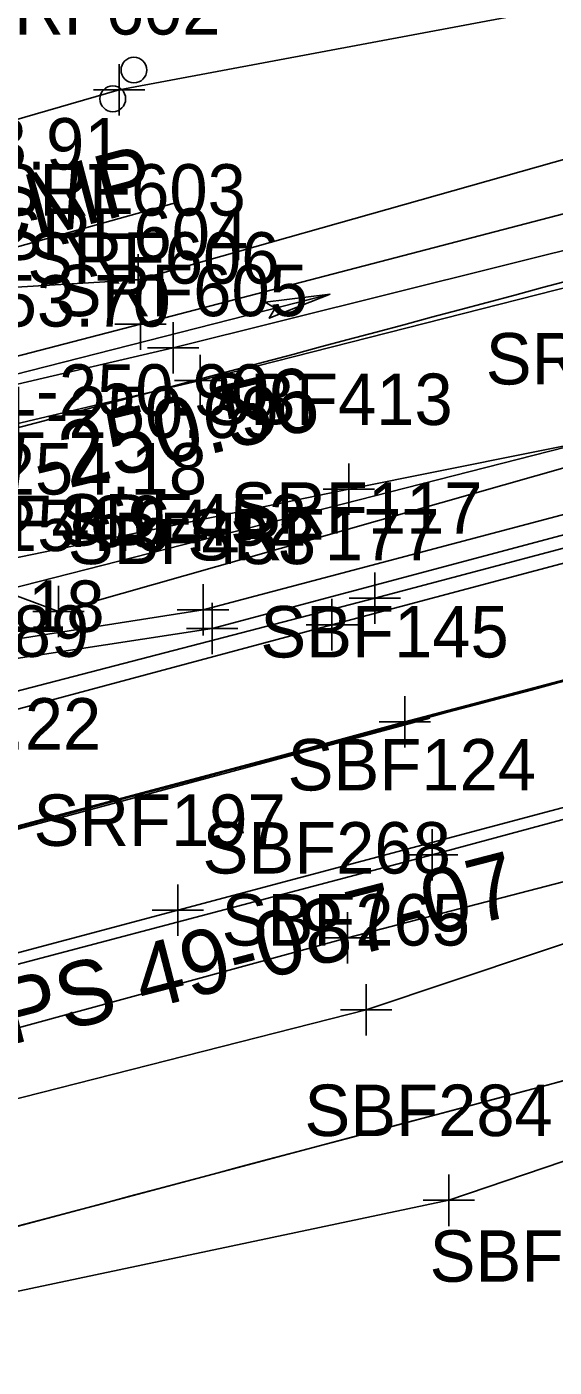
# Model space of a CAD drawing. Extents: x 818717 to 846077, y 440014 to 541392.
# Drawn here: x 831575.4 to 831616.5, y 493028.8 to 493133.1 of the extents above; entities that cross this region are included whole.
import ezdxf

# ---------------------------------------------------------------- set-up
doc = ezdxf.new("R2010")
doc.units = 0
for name, color, linetype in [('SURVEY - CENTERLINE - Preliminary', 7, 'Continuous'), ('SURVEY - CENTERLINE - Preliminary Text', 7, 'Continuous'), ('SURVEY - CONTROL with Text', 7, 'Continuous'), ('SURVEY - DRAINAGE - Area Shapes', 7, 'Continuous'), ('SURVEY - DRAINAGE - Natural Features Text', 7, 'Continuous'), ('SURVEY - DRAINAGE - Pipes and Culverts', 7, 'Continuous'), ('SURVEY - DTM - Breaklines', 7, 'Continuous'), ('SURVEY - DTM - Breaklines - Points - Elevations', 7, 'Continuous'), ('SURVEY - DTM - Breaklines - Points - Locators', 7, 'Continuous'), ('SURVEY - DTM - Breaklines - Points - Numbers', 7, 'Continuous'), ('SURVEY - DTM - Spot Points - Locators', 7, 'Continuous'), ('SURVEY - DTM - Spot Points - Point Numbers', 7, 'Continuous'), ('SURVEY - PROPERTY - ROW Lines', 7, 'Continuous'), ('SURVEY - TRAFFIC CONTROL - Pavement Marking - Points - Locators', 7, 'Continuous'), ('SURVEY - TRAFFIC CONTROL - Pavement Marking - Points - Numbers', 7, 'Continuous'), ('SURVEY - TRAFFIC CONTROL - Pavement Marking with Text', 7, 'Continuous'), ('SURVEY - TRANSPORTATION - Features - Points - Elevations', 7, 'Continuous'), ('SURVEY - TRANSPORTATION - Roads', 7, 'Continuous'), ('SURVEY - TRANSPORTATION - Roads - Points - Locators', 7, 'Continuous'), ('SURVEY - TRANSPORTATION - Roads - Points - Numbers', 7, 'Continuous'), ('SURVEY - UTILITIES - Electric (Overhead) with Text', 7, 'Continuous'), ('SURVEY - UTILITIES - Telephone (Underground) - Points - Locators', 7, 'Continuous'), ('SURVEY - UTILITIES - Telephone (Underground) - Points - Numbers', 7, 'Continuous'), ('SURVEY - UTILITIES - Telephone (Underground) with Text', 7, 'Continuous'), ('SURVEY - UTILITIES - Water with Text', 7, 'Continuous'), ('SURVEY - VEGETATION - Features - Points - Locators', 7, 'Continuous'), ('SURVEY - VEGETATION - Features - Points - Numbers', 7, 'Continuous'), ('SURVEY - VEGETATION - Features with Text', 7, 'Continuous')]:
    doc.layers.add(name, color=color, linetype=linetype)

msp = doc.modelspace()

# ---------------------------------------------------------------- linework, layer by layer
at = {"layer": 'SURVEY - CENTERLINE - Preliminary'}
msp.add_arc((818719.06, 541389.92), 50000, 284.715407, 285.043654, dxfattribs=at)
msp.add_arc((818719.06, 541389.92), 50000, 284.715407, 285.043654, dxfattribs=at)
msp.add_arc((818719.06, 541389.92), 50000, 284.715407, 285.043654, dxfattribs=at)
msp.add_arc((818719.06, 541389.92), 50000, 284.715407, 285.043654, dxfattribs=at)
at = {"layer": 'SURVEY - CENTERLINE - Preliminary Text'}
msp.add_line((831558.49, 493066.32), (831606.78, 493079.3), dxfattribs=at)
at = {"layer": 'SURVEY - DRAINAGE - Area Shapes'}
msp.add_lwpolyline([(833331.86, 493535.43), (832825.85, 493400.54), (832121.68, 493216.64), (831495.16, 493049.75), (830960.37, 492909.24), (830124.73, 492686.08), (830069.9, 493396.23), (830870.86, 494031.84), (831248.11, 494413.67), (831536.95, 494545.33), (832050.07, 494534.01), (832097.96, 494614.84), (832139.36, 494784.62), (832167.46, 494840.58), (832274.31, 494844.36), (832647.22, 494804.13), (832934.24, 494910.41), (833081.03, 494456.05), (833331.86, 493535.43)], dxfattribs=at)
at = {"layer": 'SURVEY - DRAINAGE - Natural Features Text'}
for p, q in [((831599.03, 493112.28), (831572.31, 493105.48)), ((831596.41, 493111.62), (831599.03, 493112.28))]:
    msp.add_line(p, q, dxfattribs=at)
msp.add_lwpolyline([(831599.03, 493112.28), (831594.29, 493110.41), (831594.76, 493111.2), (831593.97, 493111.67)], close=True, dxfattribs=at)
msp.add_lwpolyline([(831599.03, 493112.28), (831594.29, 493110.41), (831594.76, 493111.2), (831593.97, 493111.67), (831599.03, 493112.28)], dxfattribs=at)
at = {"layer": 'SURVEY - DRAINAGE - Pipes and Culverts'}
msp.add_lwpolyline([(831587.19, 493119.44), (831562.39, 493112.53), (831553.15, 493099.33)], dxfattribs=at)
at = {"layer": 'SURVEY - DTM - Breaklines'}
for points in [[(831744.45, 493161.42), (831733.6, 493161.48), (831718.89, 493162.93), (831693.15, 493143.85), (831664.48, 493135.93), (831635.81, 493128.01), (831584.09, 493113.39), (831556.94, 493111.76)], [(831746.03, 493150.49), (831721.99, 493159.6), (831701.71, 493140.66), (831669.96, 493132.34), (831637.08, 493123.71), (831584.27, 493109.95), (831564.6, 493104.83)], [(831745, 493144.97), (831720.93, 493155.22), (831703.76, 493138.42), (831670.77, 493129.62), (831637.8, 493120.82), (831586.82, 493108.1), (831565.35, 493103.1)], [(831741.37, 493141.89), (831719.21, 493148.15), (831699.03, 493131.87), (831668.03, 493124.84), (831637.03, 493117.81), (831588.92, 493105.57), (831559.77, 493098.7)], [(831739.77, 493125.73), (831736.96, 493133.25), (831706.03, 493122.21), (831667.13, 493111.4), (831622.43, 493100.26), (831577.9, 493087.61), (831559.93, 493094.31)], [(831172.33, 492965.05), (831181.59, 492967.43), (831227.67, 492979.44), (831274.72, 492991.66), (831322.92, 493004.21), (831368.33, 493016.26), (831413.81, 493028.29), (831465.87, 493041.9), (831511.63, 493053.91), (831556.79, 493065.9), (831604.84, 493079.03), (831650.91, 493091.16), (831699.1, 493103.99), (831742.48, 493115.71)], [(831735.74, 492991.87), (831733.95, 493031.6), (831721.42, 493066.61), (831712.04, 493082.17), (831703.34, 493084.91), (831695.58, 493084.59), (831648.81, 493072.35), (831601.83, 493056.63), (831555.35, 493044.81), (831504.59, 493031.55), (831455.34, 493020.07), (831405.51, 493005.85), (831372.59, 492995.58), (831358.62, 492993.34)], [(831661.1, 493078), (831648.02, 493074.6), (831600.39, 493062.23), (831554.15, 493049.62), (831503.9, 493035.94), (831454.34, 493024.18), (831404.79, 493010.33), (831371.1, 493001.48)], [(831362.8, 492979.81), (831376.24, 492982.73), (831405.77, 492991.28), (831454.7, 493004.49), (831506.17, 493017.71), (831556.95, 493031), (831608.27, 493041.82), (831657.28, 493058.44), (831693.45, 493071.62), (831709.12, 493073.94), (831712.7, 493059.63), (831718.93, 493040.56), (831729.91, 492991.41)]]:
    msp.add_lwpolyline(points, dxfattribs=at)
at = {"layer": 'SURVEY - DTM - Breaklines - Points - Locators'}
for p, q in [((831584.09, 493115.39), (831584.09, 493111.39)), ((831586.09, 493113.39), (831582.09, 493113.39)), ((831584.27, 493111.95), (831584.27, 493107.95)), ((831586.27, 493109.95), (831582.27, 493109.95)), ((831586.82, 493110.1), (831586.82, 493106.1)), ((831588.82, 493108.1), (831584.82, 493108.1)), ((831588.92, 493107.57), (831588.92, 493103.57)), ((831590.92, 493105.57), (831586.92, 493105.57)), ((831577.9, 493089.61), (831577.9, 493085.61)), ((831579.9, 493087.61), (831575.9, 493087.61)), ((831604.84, 493081.03), (831604.84, 493077.03)), ((831606.84, 493079.03), (831602.84, 493079.03)), ((831600.39, 493064.23), (831600.39, 493060.23)), ((831602.39, 493062.23), (831598.39, 493062.23)), ((831601.83, 493058.63), (831601.83, 493054.63)), ((831603.83, 493056.63), (831599.83, 493056.63)), ((831608.27, 493043.82), (831608.27, 493039.82)), ((831610.27, 493041.82), (831606.27, 493041.82))]:
    msp.add_line(p, q, dxfattribs=at)
at = {"layer": 'SURVEY - DTM - Spot Points - Locators'}
for centre in [(831583.76, 493129.71), (831582.12, 493127.47)]:
    msp.add_circle(centre, 1, dxfattribs=at)
at = {"layer": 'SURVEY - PROPERTY - ROW Lines'}
for radius in [49970, 50030]:
    msp.add_arc((818719.06, 541389.92), radius, 284.715401, 285.043654, dxfattribs=at)
at = {"layer": 'SURVEY - TRAFFIC CONTROL - Pavement Marking - Points - Locators'}
for p, q in [((831599.16, 493088.58), (831599.16, 493084.58)), ((831601.16, 493086.58), (831597.16, 493086.58)), ((831587.19, 493066.38), (831587.19, 493062.38)), ((831589.19, 493064.38), (831585.19, 493064.38))]:
    msp.add_line(p, q, dxfattribs=at)
at = {"layer": 'SURVEY - TRAFFIC CONTROL - Pavement Marking with Text'}
for points in [[(832159.39, 493235.77), (832116.7, 493224.52), (832072.63, 493213.17), (832030, 493201.97), (831987.46, 493190.83), (831936.58, 493177.36), (831894.1, 493165.96), (831849.46, 493153.92), (831808.03, 493142.52), (831768.36, 493131.66), (831727.87, 493120.89), (831684.5, 493109.18), (831641.68, 493097.86), (831599.16, 493086.58), (831554.58, 493074.61), (831511.86, 493063.5), (831467.07, 493051.66), (831425.05, 493040.69), (831380.34, 493029.11), (831337.84, 493017.82), (831296.13, 493006.89), (831251.61, 492995.36), (831208.94, 492984.12), (831169.87, 492973.88)], [(831174.64, 492955.97), (831217.88, 492967.4), (831260.2, 492978.43), (831305.6, 492990.16), (831350.87, 493002.2), (831397.34, 493014.25), (831441.59, 493025.83), (831487.77, 493037.91), (831534.41, 493050.33), (831587.19, 493064.38), (831630.52, 493075.92), (831676.82, 493088.3), (831723.86, 493100.96), (831758.43, 493110.25), (831806.28, 493123.18), (831848.98, 493134.67), (831896.65, 493147.52), (831940.52, 493159.26), (831989.17, 493172.11), (832037.06, 493184.69), (832086.82, 493197.77), (832134.83, 493210.3)]]:
    msp.add_lwpolyline(points, dxfattribs=at)
at = {"layer": 'SURVEY - TRANSPORTATION - Roads'}
for points in [[(831740.14, 493125.18), (831693.82, 493112.89), (831648.31, 493100.78), (831602.5, 493088.65), (831573.14, 493081.02), (831536.49, 493071.33), (831509.09, 493063.99), (831462.95, 493051.69), (831417.27, 493039.63), (831365.78, 493026.17), (831320.15, 493014.2), (831272.42, 493001.81), (831225.35, 492989.57), (831179.26, 492977.48), (831169.53, 492974.82)], [(831745.28, 493105.9), (831698.71, 493093.56), (831652.79, 493081.06), (831606.96, 493068.69), (831560.39, 493056.4), (831514.16, 493044.16), (831468.16, 493032.15), (831422.28, 493020.03), (831370.82, 493006.55), (831324.94, 492994.38), (831276.67, 492981.92), (831229.94, 492969.71), (831184.11, 492957.61), (831175.07, 492955.18)]]:
    msp.add_lwpolyline(points, dxfattribs=at)
at = {"layer": 'SURVEY - TRANSPORTATION - Roads - Points - Locators'}
for p, q in [((831602.5, 493090.65), (831602.5, 493086.65)), ((831604.5, 493088.65), (831600.5, 493088.65)), ((831606.96, 493070.69), (831606.96, 493066.69)), ((831608.96, 493068.69), (831604.96, 493068.69))]:
    msp.add_line(p, q, dxfattribs=at)
at = {"layer": 'SURVEY - UTILITIES - Electric (Overhead) with Text'}
msp.add_lwpolyline([(832667.18, 493331.74), (832415.28, 493266.23), (832147.85, 493195.27), (831907.96, 493131.64), (831666.03, 493064.14), (831375.19, 492986.65), (831101.3, 492913.04)], dxfattribs=at)
at = {"layer": 'SURVEY - UTILITIES - Telephone (Underground) - Points - Locators'}
for p, q in [((831589.14, 493089.73), (831589.14, 493085.73)), ((831589.85, 493088.29), (831589.85, 493084.29)), ((831591.14, 493087.73), (831587.14, 493087.73)), ((831591.85, 493086.29), (831587.85, 493086.29))]:
    msp.add_line(p, q, dxfattribs=at)
at = {"layer": 'SURVEY - UTILITIES - Telephone (Underground) with Text'}
for points in [[(831740.84, 493147.47), (831733.65, 493144.98), (831719.65, 493132.04), (831718.21, 493127.36), (831710.77, 493122.23), (831704.63, 493119.11), (831642.21, 493101.76), (831589.14, 493087.73), (831562.31, 493083.53), (831548.55, 493081.71), (831526.07, 493073.31), (831474.79, 493057.79), (831408.78, 493040.9), (831354.46, 493027.01)], [(831741.3, 493145.81), (831734.32, 493143.23), (831720.77, 493131.05), (831718.48, 493125.87), (831712.05, 493120.94), (831705.03, 493117.4), (831642.5, 493100.3), (831589.85, 493086.29), (831562.38, 493082.08), (831549.09, 493079.97), (831526.29, 493071.58), (831475.25, 493056.52), (831409.48, 493038.73), (831354.48, 493025.59)]]:
    msp.add_lwpolyline(points, dxfattribs=at)
at = {"layer": 'SURVEY - UTILITIES - Water with Text'}
msp.add_lwpolyline([(831168.53, 492982.83), (831221.68, 492997.59), (831271.35, 493010.03), (831320.05, 493023.02), (831382.11, 493039.09), (831464.43, 493059.02), (831521.6, 493075.98), (831637.27, 493105.47), (831699.54, 493130.69), (831734.63, 493142.29), (831763.92, 493149.4), (831800.53, 493157.83), (831844.47, 493169.57), (831878.73, 493177.18), (831933.72, 493193.59), (832000.95, 493211.25), (832058.59, 493225.48), (832113.6, 493238.29), (832172.68, 493261.93), (832217.98, 493273.66), (832269.17, 493287.2), (832330.79, 493299.45)], dxfattribs=at)
at = {"layer": 'SURVEY - VEGETATION - Features - Points - Locators'}
for p, q in [((831582.61, 493130.17), (831582.61, 493126.17)), ((831584.61, 493128.17), (831580.61, 493128.17)), ((831600.48, 493099.11), (831600.48, 493095.11)), ((831602.48, 493097.11), (831598.48, 493097.11))]:
    msp.add_line(p, q, dxfattribs=at)
at = {"layer": 'SURVEY - VEGETATION - Features with Text'}
msp.add_lwpolyline([(831643.12, 493105.66), (831600.48, 493097.11), (831561.88, 493089.17), (831554.85, 493120.14), (831582.61, 493128.17), (831628.77, 493136.82)], dxfattribs=at)

# ---------------------------------------------------------------- texts
at = {"layer": 'SURVEY - CONTROL with Text'}
msp.add_text('GPS 49-087-07', height=5, rotation=14.4863, dxfattribs=at).set_placement((831569.05, 493052.57))
at = {"layer": 'SURVEY - DRAINAGE - Pipes and Culverts'}
for s, rotation, p in [('24"CMP', 14.7678, (831561.96, 493112.86)), ('INV-250.56', 13.4974, (831565.65, 493094.06))]:
    msp.add_text(s, height=5, rotation=rotation, dxfattribs=at).set_placement(p)
at = {"layer": 'SURVEY - DTM - Breaklines - Points - Elevations'}
for s, p in [('EL-253.70', (831561.94, 493109.76)), ('EL-250.90', (831569.6, 493102.83)), ('EL-250.69', (831570.35, 493101.1)), ('EL-254.18', (831564.77, 493096.7)), ('EL-254.64', (831564.93, 493092.31)), ('EL-254.89', (831555.6, 493084.08))]:
    msp.add_text(s, height=4, dxfattribs=at).set_placement(p)
at = {"layer": 'SURVEY - DTM - Breaklines - Points - Numbers'}
for s, p in [('SRF603', (831572.85, 493118.39)), ('SRF604', (831573.03, 493114.95)), ('SRF606', (831575.47, 493113.1)), ('SRF605', (831577.68, 493110.57)), ('SRF468', (831611.14, 493105.26)), ('SRF469', (831566.64, 493092.61)), ('SBF145', (831593.6, 493084.03)), ('SBF268', (831589.1, 493067.23)), ('SBF265', (831590.59, 493061.63)), ('SBF284', (831597.03, 493046.82))]:
    msp.add_text(s, height=4, dxfattribs=at).set_placement(p)
at = {"layer": 'SURVEY - DTM - Spot Points - Point Numbers'}
for s, p in [('SRF602', (831570.88, 493132.47)), ('SBF309', (831606.77, 493035.49))]:
    msp.add_text(s, height=4, dxfattribs=at).set_placement(p)
at = {"layer": 'SURVEY - TRAFFIC CONTROL - Pavement Marking - Points - Numbers'}
for s, p in [('SRF177', (831587.92, 493091.58)), ('SRF197', (831575.95, 493069.38))]:
    msp.add_text(s, height=4, dxfattribs=at).set_placement(p)
at = {"layer": 'SURVEY - TRANSPORTATION - Features - Points - Elevations'}
for s, p in [('EL-253.91', (831558.19, 493121.97)), ('EL-255.22', (831556.54, 493076.87))]:
    msp.add_text(s, height=4, dxfattribs=at).set_placement(p)
at = {"layer": 'SURVEY - TRANSPORTATION - Roads - Points - Numbers'}
for s, p in [('SRF117', (831591.26, 493093.65)), ('SRF118', (831561.86, 493086.02)), ('SBF124', (831595.72, 493073.69))]:
    msp.add_text(s, height=4, dxfattribs=at).set_placement(p)
at = {"layer": 'SURVEY - UTILITIES - Telephone (Underground) - Points - Numbers'}
for s, p in [('SBF452', (831577.9, 493092.73)), ('SBF453', (831578.61, 493091.29))]:
    msp.add_text(s, height=4, dxfattribs=at).set_placement(p)
at = {"layer": 'SURVEY - VEGETATION - Features - Points - Numbers'}
msp.add_text('SBF413', height=4, dxfattribs=at).set_placement((831589.24, 493102.11))

doc.saveas('drawing.dxf')
